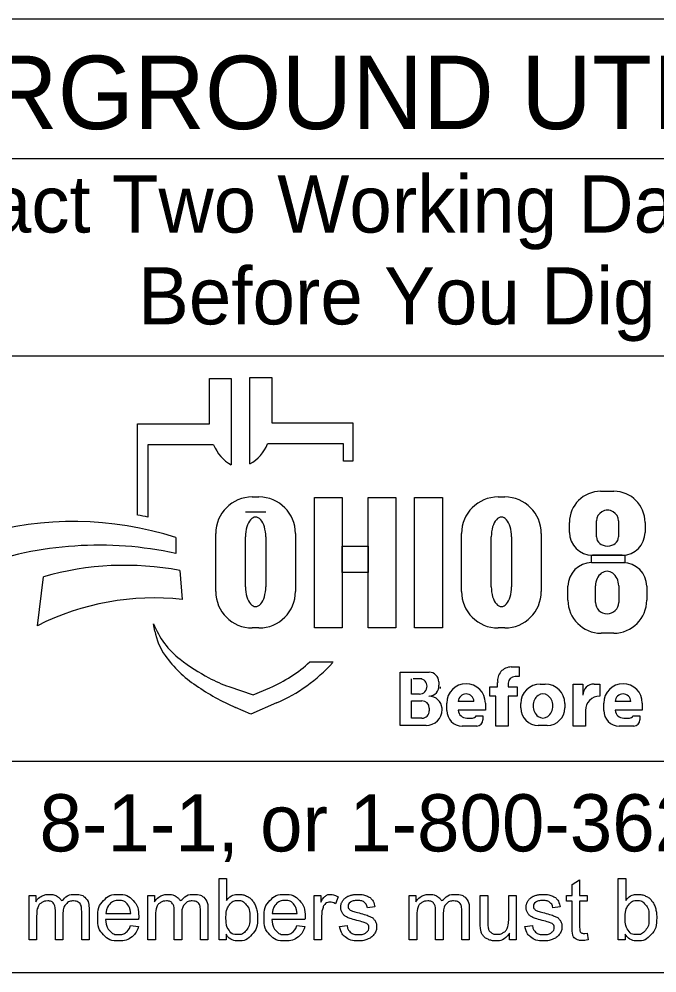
# Model space of a CAD drawing. Extents: x 0 to 34, y -5 to 22.
# Drawn here: x 3.267 to 4.831, y 2.143 to 4.48 of the extents above; entities that cross this region are included whole.
import ezdxf

# ---------------------------------------------------------------- set-up
doc = ezdxf.new("R2010")
doc.units = 0
doc.layers.add('SH_Data', color=7, linetype='Continuous')
doc.layers.add('SH_Text', color=7, linetype='Continuous')

msp = doc.modelspace()

# ---------------------------------------------------------------- linework, layer by layer
at = {"layer": 'SH_Data'}
for p, q in [((6.6275, 4.4803), (2.3775, 4.4803)), ((2.3775, 4.1387), (6.6275, 4.1387)), ((2.3775, 3.6553), (6.6275, 3.6553)), ((6.6275, 2.6607), (2.3775, 2.6607)), ((6.6275, 2.1428), (2.3775, 2.1428))]:
    msp.add_line(p, q, dxfattribs=at)
at = {"layer": 'SH_Text'}
for p, q in [((3.7335, 3.4883), (3.7335, 3.5998)), ((3.7335, 3.5998), (3.7872, 3.5998)), ((3.7872, 3.5998), (3.7872, 3.3877)), ((3.8329, 3.39), (3.8329, 3.6021)), ((3.8329, 3.6021), (3.8865, 3.6021)), ((3.8865, 3.6021), (3.8865, 3.4906)), ((3.5576, 3.2644), (3.5576, 3.4883)), ((3.5576, 3.4883), (3.7335, 3.4883)), ((3.8865, 3.4906), (4.0857, 3.4906)), ((4.0857, 3.4906), (4.0857, 3.3968)), ((3.5828, 3.4369), (3.5828, 3.26)), ((3.7439, 3.4369), (3.5828, 3.4369)), ((4.0625, 3.4392), (3.8761, 3.4392)), ((4.0625, 3.3968), (4.0625, 3.4392)), ((4.0857, 3.3968), (4.0625, 3.3968)), ((4.6931, 3.3231), (4.7258, 3.3231)), ((3.8385, 3.3091), (3.8551, 3.3091)), ((4.4416, 3.3091), (4.4581, 3.3091)), ((3.8718, 3.2721), (3.822, 3.2721)), ((4.683, 3.2111), (4.683, 3.2504)), ((4.7371, 3.2504), (4.7371, 3.2111)), ((4.6168, 3.2225), (4.6168, 3.2468)), ((4.8022, 3.2468), (4.8022, 3.2225)), ((3.6509, 3.2097), (3.6509, 3.1709)), ((3.7491, 3.0776), (3.7491, 3.2196)), ((3.822, 3.089), (3.822, 3.2114)), ((3.8718, 3.2114), (3.8718, 3.089)), ((3.9445, 3.2196), (3.9445, 3.0776)), ((4.3521, 3.0776), (4.3521, 3.2196)), ((4.425, 3.089), (4.425, 3.2114)), ((4.4748, 3.2114), (4.4748, 3.089)), ((4.5476, 3.2196), (4.5476, 3.0776)), ((4.7462, 3.1665), (4.6728, 3.1665)), ((4.671, 3.1482), (4.7483, 3.1482)), ((3.312, 2.9936), (3.3267, 3.1137)), ((3.6608, 3.1291), (3.6671, 3.0582)), ((4.6131, 3.0563), (4.6131, 3.0903)), ((4.6806, 3.0503), (4.6806, 3.0912)), ((4.7374, 3.0912), (4.7374, 3.0503)), ((4.8062, 3.0903), (4.8062, 3.0563)), ((3.5997, 2.9807), (3.5967, 2.9986)), ((3.8551, 2.9882), (3.8385, 2.9882)), ((4.4581, 2.9882), (4.4416, 2.9882)), ((4.7252, 2.9753), (4.6941, 2.9753)), ((3.98, 2.9048), (4.0375, 2.9048)), ((4.2013, 2.749), (4.2013, 2.8798)), ((4.2013, 2.8798), (4.2725, 2.8798)), ((4.4739, 2.8926), (4.4934, 2.8926)), ((4.4934, 2.8926), (4.4934, 2.8696)), ((4.2293, 2.8263), (4.2293, 2.8632)), ((4.2545, 2.8632), (4.2332, 2.8632)), ((4.2963, 2.856), (4.2963, 2.8481)), ((4.4406, 2.8442), (4.4406, 2.8546)), ((4.4667, 2.8526), (4.4667, 2.8442)), ((4.4934, 2.8691), (4.4832, 2.8691)), ((3.7816, 2.8444), (3.841, 2.8239)), ((3.841, 2.8239), (3.8821, 2.8417)), ((4.4213, 2.8212), (4.4213, 2.8442)), ((4.4213, 2.8442), (4.4406, 2.8442)), ((4.4667, 2.8442), (4.4883, 2.8442)), ((4.4883, 2.8442), (4.4883, 2.8212)), ((4.5451, 2.8508), (4.5573, 2.8508)), ((4.6254, 2.7478), (4.6254, 2.8505)), ((4.6254, 2.8505), (4.6499, 2.8505)), ((4.6499, 2.8505), (4.6499, 2.8237)), ((4.6772, 2.8505), (4.691, 2.8505)), ((4.691, 2.8505), (4.691, 2.8209)), ((4.2487, 2.8263), (4.2293, 2.8263)), ((4.2293, 2.7669), (4.2293, 2.8097)), ((4.2293, 2.8097), (4.2548, 2.8097)), ((4.3824, 2.8082), (4.3439, 2.8082)), ((4.4362, 2.8212), (4.4213, 2.8212)), ((4.4362, 2.7478), (4.4362, 2.8212)), ((4.4883, 2.8212), (4.4667, 2.8212)), ((4.4667, 2.8212), (4.4667, 2.7478)), ((4.7674, 2.8082), (4.7288, 2.8082)), ((3.835, 2.7769), (3.7976, 2.7934)), ((3.8983, 2.8044), (3.835, 2.7769)), ((4.2729, 2.7916), (4.2729, 2.7853)), ((4.3043, 2.7887), (4.3043, 2.7884)), ((4.3159, 2.7858), (4.3159, 2.8042)), ((4.4104, 2.7866), (4.344, 2.7866)), ((4.4104, 2.8042), (4.4104, 2.7866)), ((4.4973, 2.7922), (4.4973, 2.8029)), ((4.6051, 2.8029), (4.6051, 2.7922)), ((4.6559, 2.786), (4.6559, 2.7478)), ((4.7008, 2.7858), (4.7008, 2.8042)), ((4.7953, 2.7866), (4.7289, 2.7866)), ((4.7953, 2.8042), (4.7953, 2.7866)), ((4.2546, 2.7669), (4.2293, 2.7669)), ((4.3649, 2.7673), (4.379, 2.7673)), ((4.3876, 2.7729), (4.4045, 2.7729)), ((4.4045, 2.7729), (4.4045, 2.7631)), ((4.7498, 2.7673), (4.7639, 2.7673)), ((4.7725, 2.7729), (4.7894, 2.7729)), ((4.7894, 2.7729), (4.7894, 2.7631)), ((4.265, 2.749), (4.2013, 2.749)), ((4.3892, 2.7478), (4.3538, 2.7478)), ((4.4667, 2.7478), (4.4362, 2.7478)), ((4.5623, 2.7494), (4.5401, 2.7494)), ((4.6559, 2.7478), (4.6254, 2.7478)), ((4.7742, 2.7478), (4.7388, 2.7478))]:
    msp.add_line(p, q, dxfattribs=at)
for points in [[(3.991, 3.3081), (4.0589, 3.3081), (4.0589, 2.9881), (3.991, 2.9881)], [(4.1231, 3.3081), (4.1911, 3.3081), (4.1911, 2.9881), (4.1231, 2.9881)], [(4.2364, 3.3081), (4.3052, 3.3081), (4.3052, 2.9881), (4.2364, 2.9881)], [(4.0589, 3.1882), (4.1231, 3.1882), (4.1231, 3.1242), (4.0589, 3.1242)], [(4.6706, 3.1665), (4.7523, 3.1665), (4.7523, 3.1481), (4.6706, 3.1481)]]:
    msp.add_lwpolyline(points, close=True, dxfattribs=at)
for points in [[(3.7743, 2.2239), (3.7573, 2.2239), (3.7573, 2.3741), (3.7757, 2.3741), (3.7757, 2.3206)], [(4.6233, 2.2558), (4.6233, 2.3185), (4.6097, 2.3185), (4.6097, 2.3328), (4.6233, 2.3328), (4.6233, 2.3597), (4.6417, 2.3708), (4.6417, 2.3328), (4.6601, 2.3328), (4.6601, 2.3185), (4.6417, 2.3185), (4.6417, 2.2547)], [(4.7534, 2.2239), (4.7363, 2.2239), (4.7363, 2.3741), (4.7548, 2.3741), (4.7548, 2.3206)], [(3.2912, 2.2239), (3.2912, 2.3328), (3.3077, 2.3328), (3.3077, 2.3174)], [(3.5826, 2.2239), (3.5826, 2.3328), (3.5991, 2.3328), (3.5991, 2.3174)], [(3.9904, 2.2239), (3.9904, 2.3328), (4.007, 2.3328), (4.007, 2.3163)], [(4.0495, 2.3293), (4.043, 2.3122)], [(4.2236, 2.2239), (4.2236, 2.3328), (4.2401, 2.3328), (4.2401, 2.3174)], [(4.3979, 2.2654), (4.3979, 2.3328), (4.4164, 2.3328), (4.4164, 2.2724)], [(4.4676, 2.2745), (4.4676, 2.3328), (4.4861, 2.3328), (4.4861, 2.2239), (4.4696, 2.2239)], [(3.3743, 2.2871), (3.3743, 2.2239), (3.3559, 2.2239), (3.3559, 2.2946)], [(3.4388, 2.2986), (3.4388, 2.2239), (3.4203, 2.2239), (3.4203, 2.2924)], [(3.6657, 2.2871), (3.6657, 2.2239), (3.6473, 2.2239), (3.6473, 2.2946)], [(3.7301, 2.2986), (3.7301, 2.2239), (3.7117, 2.2239), (3.7117, 2.2924)], [(4.1394, 2.3046), (4.1213, 2.3022)], [(4.3067, 2.2871), (4.3067, 2.2239), (4.2883, 2.2239), (4.2883, 2.2946)], [(4.3711, 2.2986), (4.3711, 2.2239), (4.3527, 2.2239), (4.3527, 2.2924)], [(4.594, 2.3046), (4.5759, 2.3022)], [(3.3097, 2.2803), (3.3097, 2.2239), (3.2912, 2.2239)], [(3.56, 2.2736), (3.4788, 2.2736)], [(3.4799, 2.2887), (3.5406, 2.2887)], [(3.601, 2.2803), (3.601, 2.2239), (3.5826, 2.2239)], [(3.968, 2.2736), (3.8868, 2.2736)], [(3.8879, 2.2887), (3.9486, 2.2887)], [(4.0088, 2.2809), (4.0088, 2.2239), (3.9904, 2.2239)], [(4.242, 2.2803), (4.242, 2.2239), (4.2236, 2.2239)], [(3.5404, 2.2591), (3.5595, 2.2567)], [(3.9484, 2.2591), (3.9675, 2.2567)], [(4.053, 2.2564), (4.0712, 2.2593)], [(4.5076, 2.2564), (4.5258, 2.2593)], [(3.7743, 2.2375), (3.7743, 2.2239)], [(4.4696, 2.2239), (4.4696, 2.24)], [(4.6601, 2.2404), (4.6628, 2.2241)], [(4.7534, 2.2375), (4.7534, 2.2239)]]:
    msp.add_lwpolyline(points, dxfattribs=at)
for centre, radius, start, end in [((3.8353, 3.4736), 0.0985, 201.9296, 240.7469), ((3.7847, 3.476), 0.0985, 299.2531, 338.0704), ((4.6931, 3.2468), 0.0763, 90, 180), ((4.7258, 3.2468), 0.0763, 0, 90), ((3.8385, 3.2196), 0.0895, 90, 180), ((3.8551, 3.2196), 0.0895, 0, 90), ((4.4416, 3.2196), 0.0895, 90, 180), ((4.4581, 3.2196), 0.0895, 0, 90), ((3.3997, 2.4302), 0.8191, 72.1402, 106.3144), ((3.4295, 2.4554), 0.8191, 79.2074, 81.0007), ((4.6728, 3.2225), 0.056, 180, 270), ((4.7462, 3.2225), 0.056, 270, 0), ((3.4628, 2.2991), 0.8919, 77.8238, 109.8274), ((3.5267, 2.4094), 0.7322, 79.44, 105.8467), ((4.671, 3.0903), 0.0579, 90, 180), ((4.7483, 3.0903), 0.0579, 0, 90), ((3.8385, 3.0776), 0.0895, 180, 270), ((3.8551, 3.0776), 0.0895, 270, 0), ((4.4416, 3.0776), 0.0895, 180, 270), ((4.4581, 3.0776), 0.0895, 270, 0), ((3.5987, 2.4262), 0.6357, 83.8248, 116.8021), ((4.6941, 3.0563), 0.081, 180, 270), ((4.7252, 3.0563), 0.081, 270, 0), ((3.7841, 3.0707), 0.2008, 201.0457, 232.5314), ((3.741, 3.0048), 0.1433, 189.6817, 216.0884), ((3.8747, 3.1022), 0.3088, 216.0884, 235.7167), ((3.9766, 3.3219), 0.5173, 232.5314, 241.794), ((3.7387, 3.1722), 0.3602, 293.4582, 312.0712), ((3.7387, 3.1722), 0.401, 293.4582, 317.8286), ((4.2725, 2.856), 0.0238, 0, 90), ((4.4739, 2.859), 0.0335, 90, 187.5187), ((3.8914, 3.1631), 0.3371, 241.794, 250.9821), ((4.2505, 2.8463), 0.0169, 357.8325, 90), ((4.4832, 2.8526), 0.0165, 90, 180), ((4.0412, 3.3465), 0.6044, 235.7167, 246.2325), ((4.2487, 2.845), 0.0187, 270, 2.0582), ((4.2721, 2.8453), 0.0243, 270, 6.6529), ((4.2827, 2.8438), 0.0175, 347.4023, 0), ((4.3631, 2.8042), 0.0473, 0, 180), ((4.5451, 2.8029), 0.0478, 90, 180), ((4.5573, 2.8029), 0.0478, 0, 90), ((4.6768, 2.8237), 0.0269, 89.2449, 180), ((4.7481, 2.8042), 0.0473, 0, 180), ((4.2548, 2.7916), 0.0181, 0, 90), ((4.2722, 2.7889), 0.0321, 4.0748, 90), ((4.3632, 2.8072), 0.0193, 2.9632, 177.0368), ((4.6908, 2.786), 0.0349, 89.6033, 180), ((4.7481, 2.8072), 0.0193, 2.9632, 177.0368), ((4.2546, 2.7853), 0.0184, 270, 0), ((4.265, 2.7884), 0.0393, 270, 0), ((4.2714, 2.7887), 0.033, 0, 11.7502), ((4.3538, 2.7858), 0.038, 180, 270), ((4.3649, 2.7883), 0.021, 184.827, 270), ((4.5401, 2.7922), 0.0428, 180, 270), ((4.5623, 2.7922), 0.0428, 270, 0), ((4.7388, 2.7858), 0.038, 180, 270), ((4.7498, 2.7883), 0.021, 184.827, 270), ((4.379, 2.7767), 0.00938, 270, 335.9979), ((4.3892, 2.7631), 0.0152, 270, 0), ((4.7639, 2.7767), 0.00938, 270, 335.9979), ((4.7742, 2.7631), 0.0152, 270, 0)]:
    msp.add_arc(centre, radius, start, end, dxfattribs=at)
for centre, major_axis, ratio, start_param, end_param in [((4.71, 3.2504), (0.0271, 0), 0.969373, 0, 3.141593), ((3.8469, 3.2114), (0, 0.0484), 0.514403, 4.712389, 7.853982), ((4.4499, 3.2114), (0, 0.0484), 0.514403, 4.712389, 7.853982), ((4.71, 3.2111), (0.0271, 0), 0.818453, 3.141593, 6.283185), ((4.709, 3.0912), (0, 0.0358), 0.794529, 4.712389, 7.853982), ((3.8469, 3.089), (0, 0.0484), 0.514403, 1.570796, 4.712389), ((4.4499, 3.089), (0, 0.0484), 0.514403, 1.570796, 4.712389), ((4.709, 3.0503), (0.0284, 0), 0.959837, 3.141593, 6.283185), ((4.5517, 2.7976), (0, 0.029), 0.832186, 4.712389, 7.853982), ((4.5517, 2.7976), (0, 0.0302), 0.797287, 1.570796, 4.712389)]:
    msp.add_ellipse(centre, major_axis=major_axis, ratio=ratio, start_param=start_param, end_param=end_param, dxfattribs=at)
for points in [[(3.3077, 2.3174), (3.3128, 2.3254), (3.3214, 2.3303), (3.3299, 2.3352), (3.3407, 2.3352), (3.3528, 2.3352), (3.3606, 2.3301), (3.3683, 2.3251), (3.3715, 2.3161), (3.3844, 2.3352), (3.4051, 2.3352), (3.4213, 2.3352), (3.43, 2.3262), (3.4388, 2.3172), (3.4388, 2.2986)], [(3.3559, 2.2946), (3.3559, 2.3069), (3.3514, 2.313), (3.3469, 2.3191), (3.3366, 2.3191), (3.3288, 2.3191), (3.3222, 2.315), (3.3156, 2.311), (3.3126, 2.3031), (3.3097, 2.2952), (3.3097, 2.2803)], [(3.4203, 2.2924), (3.4203, 2.3035), (3.4185, 2.3083), (3.4168, 2.3132), (3.412, 2.3162), (3.4073, 2.3191), (3.401, 2.3191), (3.3895, 2.3191), (3.3819, 2.3115), (3.3743, 2.3039), (3.3743, 2.2871)], [(3.5595, 2.2567), (3.555, 2.24), (3.5428, 2.2307), (3.5306, 2.2215), (3.5117, 2.2215), (3.4878, 2.2215), (3.4738, 2.2362), (3.4598, 2.2509), (3.4598, 2.2774), (3.4598, 2.3049), (3.474, 2.32), (3.4881, 2.3352), (3.5106, 2.3352), (3.5324, 2.3352), (3.5463, 2.3203), (3.5601, 2.3055), (3.5601, 2.2785), (3.5601, 2.2769), (3.56, 2.2736)], [(3.5406, 2.2887), (3.5394, 2.3025), (3.5337, 2.3094), (3.5249, 2.3201), (3.5108, 2.3201), (3.4981, 2.3201), (3.4894, 2.3115), (3.4808, 2.303), (3.4799, 2.2887)], [(3.5991, 2.3174), (3.6042, 2.3254), (3.6127, 2.3303), (3.6212, 2.3352), (3.6321, 2.3352), (3.6442, 2.3352), (3.6519, 2.3301), (3.6597, 2.3251), (3.6628, 2.3161), (3.6758, 2.3352), (3.6965, 2.3352), (3.7127, 2.3352), (3.7214, 2.3262), (3.7301, 2.3172), (3.7301, 2.2986)], [(3.6473, 2.2946), (3.6473, 2.3069), (3.6428, 2.313), (3.6383, 2.3191), (3.628, 2.3191), (3.6202, 2.3191), (3.6136, 2.315), (3.607, 2.311), (3.604, 2.3031), (3.601, 2.2952), (3.601, 2.2803)], [(3.7117, 2.2924), (3.7117, 2.3035), (3.7099, 2.3083), (3.7081, 2.3132), (3.7034, 2.3162), (3.6987, 2.3191), (3.6923, 2.3191), (3.6809, 2.3191), (3.6733, 2.3115), (3.6657, 2.3039), (3.6657, 2.2871)], [(3.7741, 2.2792), (3.7741, 2.2596), (3.7794, 2.2509), (3.7881, 2.2366), (3.8029, 2.2366), (3.815, 2.2366), (3.8238, 2.2471), (3.8326, 2.2576), (3.8326, 2.2784), (3.8326, 2.2998), (3.8241, 2.3099), (3.8157, 2.3201), (3.8038, 2.3201), (3.7917, 2.3201), (3.7829, 2.3096), (3.7741, 2.299), (3.7741, 2.2792)], [(3.7757, 2.3206), (3.7874, 2.3352), (3.8055, 2.3352), (3.8155, 2.3352), (3.8245, 2.3311), (3.8335, 2.3271), (3.8392, 2.3198), (3.845, 2.3124), (3.8483, 2.3021), (3.8516, 2.2918), (3.8516, 2.28), (3.8516, 2.252), (3.8378, 2.2368), (3.8239, 2.2215), (3.8046, 2.2215), (3.7853, 2.2215), (3.7743, 2.2375)], [(3.9675, 2.2567), (3.963, 2.24), (3.9508, 2.2307), (3.9386, 2.2215), (3.9196, 2.2215), (3.8958, 2.2215), (3.8818, 2.2362), (3.8678, 2.2509), (3.8678, 2.2774), (3.8678, 2.3049), (3.882, 2.32), (3.8961, 2.3352), (3.9186, 2.3352), (3.9404, 2.3352), (3.9543, 2.3203), (3.9681, 2.3055), (3.9681, 2.2785), (3.9681, 2.2769), (3.968, 2.2736)], [(3.9486, 2.2887), (3.9474, 2.3025), (3.9417, 2.3094), (3.9328, 2.3201), (3.9188, 2.3201), (3.9061, 2.3201), (3.8974, 2.3115), (3.8888, 2.303), (3.8879, 2.2887)], [(4.007, 2.3163), (4.0133, 2.3278), (4.0187, 2.3315), (4.0241, 2.3352), (4.0305, 2.3352), (4.0398, 2.3352), (4.0495, 2.3293)], [(4.043, 2.3122), (4.0363, 2.3162), (4.0295, 2.3162), (4.0235, 2.3162), (4.0187, 2.3125), (4.0139, 2.3089), (4.0119, 2.3024), (4.0088, 2.2926), (4.0088, 2.2809)], [(4.1213, 2.3022), (4.1201, 2.3106), (4.1142, 2.3153), (4.1083, 2.3201), (4.0975, 2.3201), (4.0848, 2.3201), (4.0794, 2.3159), (4.0739, 2.3116), (4.0739, 2.306), (4.0739, 2.3024), (4.0762, 2.2995), (4.0785, 2.2966), (4.0833, 2.2946), (4.086, 2.2936), (4.0996, 2.2899), (4.1192, 2.2847), (4.1269, 2.2813), (4.1347, 2.278), (4.1391, 2.2717), (4.1435, 2.2653), (4.1435, 2.2559), (4.1435, 2.2467), (4.1381, 2.2386), (4.1327, 2.2304), (4.1226, 2.226), (4.1124, 2.2215), (4.0996, 2.2215), (4.0784, 2.2215), (4.0672, 2.2303), (4.0561, 2.2391), (4.053, 2.2564)], [(4.0712, 2.2593), (4.0727, 2.2483), (4.0798, 2.2425), (4.0868, 2.2366), (4.0995, 2.2366), (4.1122, 2.2366), (4.1184, 2.2418), (4.1245, 2.247), (4.1245, 2.254), (4.1245, 2.2602), (4.1191, 2.2638), (4.1153, 2.2663), (4.1002, 2.2701), (4.0799, 2.2752), (4.072, 2.2789), (4.0642, 2.2827), (4.0601, 2.2893), (4.0561, 2.2959), (4.0561, 2.3038), (4.0561, 2.3111), (4.0594, 2.3173), (4.0628, 2.3235), (4.0685, 2.3276), (4.0728, 2.3308), (4.0803, 2.333), (4.0877, 2.3352), (4.0962, 2.3352), (4.109, 2.3352), (4.1187, 2.3315), (4.1284, 2.3278), (4.133, 2.3215), (4.1377, 2.3152), (4.1394, 2.3046)], [(4.2401, 2.3174), (4.2452, 2.3254), (4.2537, 2.3303), (4.2622, 2.3352), (4.2731, 2.3352), (4.2852, 2.3352), (4.2929, 2.3301), (4.3007, 2.3251), (4.3038, 2.3161), (4.3168, 2.3352), (4.3375, 2.3352), (4.3537, 2.3352), (4.3624, 2.3262), (4.3711, 2.3172), (4.3711, 2.2986)], [(4.2883, 2.2946), (4.2883, 2.3069), (4.2838, 2.313), (4.2793, 2.3191), (4.269, 2.3191), (4.2612, 2.3191), (4.2546, 2.315), (4.248, 2.311), (4.245, 2.3031), (4.242, 2.2952), (4.242, 2.2803)], [(4.3527, 2.2924), (4.3527, 2.3035), (4.3509, 2.3083), (4.3491, 2.3132), (4.3444, 2.3162), (4.3397, 2.3191), (4.3333, 2.3191), (4.3219, 2.3191), (4.3143, 2.3115), (4.3067, 2.3039), (4.3067, 2.2871)], [(4.5759, 2.3022), (4.5747, 2.3106), (4.5688, 2.3153), (4.5629, 2.3201), (4.5521, 2.3201), (4.5394, 2.3201), (4.5339, 2.3159), (4.5285, 2.3116), (4.5285, 2.306), (4.5285, 2.3024), (4.5308, 2.2995), (4.533, 2.2966), (4.5378, 2.2946), (4.5406, 2.2936), (4.5542, 2.2899), (4.5737, 2.2847), (4.5815, 2.2813), (4.5893, 2.278), (4.5937, 2.2717), (4.5981, 2.2653), (4.5981, 2.2559), (4.5981, 2.2467), (4.5927, 2.2386), (4.5873, 2.2304), (4.5772, 2.226), (4.567, 2.2215), (4.5542, 2.2215), (4.5329, 2.2215), (4.5218, 2.2303), (4.5107, 2.2391), (4.5076, 2.2564)], [(4.5258, 2.2593), (4.5273, 2.2483), (4.5343, 2.2425), (4.5414, 2.2366), (4.554, 2.2366), (4.5668, 2.2366), (4.5729, 2.2418), (4.5791, 2.247), (4.5791, 2.254), (4.5791, 2.2602), (4.5736, 2.2638), (4.5698, 2.2663), (4.5548, 2.2701), (4.5345, 2.2752), (4.5266, 2.2789), (4.5188, 2.2827), (4.5147, 2.2893), (4.5107, 2.2959), (4.5107, 2.3038), (4.5107, 2.3111), (4.514, 2.3173), (4.5173, 2.3235), (4.5231, 2.3276), (4.5274, 2.3308), (4.5348, 2.333), (4.5423, 2.3352), (4.5508, 2.3352), (4.5636, 2.3352), (4.5733, 2.3315), (4.583, 2.3278), (4.5876, 2.3215), (4.5922, 2.3152), (4.594, 2.3046)], [(4.7532, 2.2792), (4.7532, 2.2596), (4.7585, 2.2509), (4.7672, 2.2366), (4.782, 2.2366), (4.7941, 2.2366), (4.8029, 2.2471), (4.8116, 2.2576), (4.8116, 2.2784), (4.8116, 2.2998), (4.8032, 2.3099), (4.7948, 2.3201), (4.7828, 2.3201), (4.7708, 2.3201), (4.762, 2.3096), (4.7532, 2.299), (4.7532, 2.2792)], [(4.7548, 2.3206), (4.7664, 2.3352), (4.7846, 2.3352), (4.7946, 2.3352), (4.8036, 2.3311), (4.8125, 2.3271), (4.8183, 2.3198), (4.8241, 2.3124), (4.8274, 2.3021), (4.8306, 2.2918), (4.8306, 2.28), (4.8306, 2.252), (4.8168, 2.2368), (4.803, 2.2215), (4.7836, 2.2215), (4.7644, 2.2215), (4.7534, 2.2375)], [(3.4788, 2.2736), (3.4799, 2.2557), (3.489, 2.2462), (3.4981, 2.2366), (3.5117, 2.2366), (3.5219, 2.2366), (3.5291, 2.242), (3.5362, 2.2473), (3.5404, 2.2591)], [(3.8868, 2.2736), (3.8879, 2.2557), (3.897, 2.2462), (3.9061, 2.2366), (3.9197, 2.2366), (3.9299, 2.2366), (3.937, 2.242), (3.9442, 2.2473), (3.9484, 2.2591)], [(4.4164, 2.2724), (4.4164, 2.258), (4.4175, 2.253), (4.4192, 2.2457), (4.4249, 2.2416), (4.4305, 2.2374), (4.4388, 2.2374), (4.4471, 2.2374), (4.4543, 2.2417), (4.4616, 2.2459), (4.4646, 2.2533), (4.4676, 2.2606), (4.4676, 2.2745)], [(4.4696, 2.24), (4.4569, 2.2215), (4.4351, 2.2215), (4.4255, 2.2215), (4.4171, 2.2252), (4.4088, 2.2289), (4.4047, 2.2345), (4.4007, 2.2401), (4.3991, 2.2482), (4.3979, 2.2536), (4.3979, 2.2654)], [(4.6628, 2.2241), (4.655, 2.2224), (4.6488, 2.2224), (4.6388, 2.2224), (4.6333, 2.2256), (4.6278, 2.2288), (4.6255, 2.234), (4.6233, 2.2392), (4.6233, 2.2558)], [(4.6417, 2.2547), (4.6417, 2.2468), (4.6427, 2.2445), (4.6436, 2.2423), (4.6458, 2.2409), (4.648, 2.2396), (4.6521, 2.2396), (4.6551, 2.2396), (4.6601, 2.2404)]]:
    msp.add_open_spline(points, degree=3, dxfattribs=at)

# ---------------------------------------------------------------- texts
for s, height, p in [('UNDERGROUND UTILITIES', 0.18, (2.5057, 4.2106)), ('Contact Two Working Days', 0.14, (2.7972, 3.9571)), ('Before You Dig', 0.14, (3.5583, 3.7321)), ('OHIO811, 8-1-1, or 1-800-362-2764', 0.14, (2.422, 2.4406))]:
    msp.add_text(s, height=height, dxfattribs=at).set_placement(p)

doc.saveas('drawing.dxf')
